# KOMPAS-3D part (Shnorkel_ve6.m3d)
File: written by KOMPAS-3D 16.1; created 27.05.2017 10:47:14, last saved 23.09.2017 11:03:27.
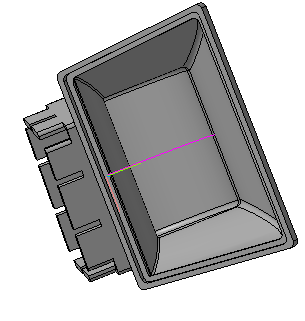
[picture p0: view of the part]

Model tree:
1. Смещенная плоскость:1
     Расстояние = 30
2. Эскиз:1
3. Эскиз:2
4. Смещенная плоскость:2
     Расстояние = 10
5. Эскиз:3
6. Плоскость через ребро и грань:1
7. Смещенная плоскость:3
     Расстояние = 10
8. Эскиз:4
9. Эскиз:5
10. Эскиз:6
11. Эскиз:7
12. Кинематическая операция:6
     Толщина стенки 1 = 4
13. Кинематическая операция:7
     Толщина стенки 1 = 4
14. Смещенная плоскость:4
     Расстояние = 4
15. Эскиз:8
16. Эскиз:9
17. Кинематическая операция:8
     Толщина стенки 1 = 4
18. Операция по сечениям:8
     Толщина стенки 1 = 4; Толщина стенки 2 = 4
19. Плоскость под углом:1
     Угол = 25
20. Смещенная плоскость:7
     Расстояние = 31
21. Эскиз:10
22. Операция по сечениям:9
     Толщина стенки 1 = 4
23. Смещенная плоскость:8
     Расстояние = 1
24. Плоскость через два ребра:1
25. Эскиз:13
26. Операция выдавливания:3
     Расстояние 1 = 8
27. Эскиз:14
28. Вырезать элемент выдавливания:8
     Расстояние 1 = 5
29. Скругление:1
     Радиус = 3
30. Скругление:2
     Радиус = 3
31. Скругление:3
     Радиус = 3
32. Скругление:4
     Радиус = 3
33. Эскиз:33
34. Вырезать элемент выдавливания:9
     Расстояние 1 = 25
35. Эскиз:34
36. Вырезать элемент выдавливания:10
     Расстояние 1 = 15
37. Эскиз:35
38. Операция выдавливания:5
     Расстояние 1 = 1
39. Эскиз:36
40. Операция выдавливания:6
     Расстояние 1 = 1
41. Скругление:29
     Радиус = 2
42. Скругление:30
     Радиус = 2
43. Скругление:31
     Радиус = 2
44. Скругление:33
     Радиус = 2
45. Скругление:34
     Радиус = 4
46. Скругление:36
     Радиус = 2
47. Скругление:37
     Радиус = 2
48. Скругление:38
     Радиус = 2
49. Скругление:39
     Радиус = 2
50. Скругление:40
     Радиус = 4
51. Скругление:41
     Радиус = 4
52. Скругление:42
     Радиус = 4
53. Скругление:43
     Радиус = 4
54. Скругление:44
     Радиус = 2
55. Скругление:45
     Радиус = 2
56. Скругление:46
     Радиус = 2
57. Скругление:47
     Радиус = 2
58. Скругление:49
     Радиус = 3
59. Скругление:50
     Радиус = 3
60. Скругление:52
     Радиус = 2
61. Скругление:53
     Радиус = 1
62. Скругление:54
     Радиус = 3
63. Скругление:55
     Радиус = 3
64. Скругление:56
     Радиус = 3
65. Скругление:57
     Радиус = 0.5
66. Скругление:58
     Радиус = 3
67. Скругление:59
     Радиус = 3
68. Скругление:60
     Радиус = 3
69. Скругление:62
     Радиус = 0.5

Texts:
  Space Bd BT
